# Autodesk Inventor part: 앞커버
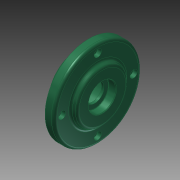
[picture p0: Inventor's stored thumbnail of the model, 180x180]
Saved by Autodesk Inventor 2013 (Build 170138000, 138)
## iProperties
Created: 2015-11
Part Number: 앞커버
Material: 알루미늄 6061
Document SubType Name: Modeling
Designer: mduedu
Density: 2.71 g/cm^3
Mass: 261.017 g
Surface Area: 221.215 cm^2
Volume: 96.3164 cm^3
Author: mduedu
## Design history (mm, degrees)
sketch "스케치1"
  geometry: C1 r 47.5 at (0, 0); 1 further point
  constraints: 1 centre point, 1 coincident
  dimensions: "d57" = 95 diameter of C1
extrude "돌출1" new body sketch "스케치1" distance "d3" = 10; taper "d4" = 0 deg
sketch "스케치2"
  geometry: C1 r 30 at (0, 0); 1 further point
  constraints: 1 centre point, 1 coincident
  dimensions: "d5" = 60 diameter of C1
extrude "돌출2" join sketch "스케치2" distance "d6" = 5; taper "d7" = -30 deg
sketch "스케치3" dims "d58" = 78
  geometry: 3 further points
  constraints: 2 vertical alignment, 1 coincident, 2 other
hole "구멍1" sketch "스케치3" at (0, 39) diameter "d11" = 4.5; stored, may be unused: countersink angle "d15" = 90 deg, drill point angle "d17" = 118 deg; dims "d12" = 6, "d13" = 8, "d14" = 4.4, "d16" = 8
sketch "스케치4"
  geometry: C1 r 32.5 at (0, 0); 1 further point
  constraints: 1 centre point, 1 coincident
  dimensions: "d21" = 65 diameter of C1
extrude "돌출3" join sketch "스케치4" distance "d23" = 12; taper "d24" = 0 deg
hole "구멍2" diameter "d27" = 34; stored, may be unused: countersink angle "d31" = 90 deg, drill point angle "d33" = 0 deg; dims "d28" = 6, "d29" = 40, "d30" = 12, "d32" = 16, "d68" = 10, "d69" = 10
fillet "모깎기3" dims "d36" = 3
fillet "모깎기4" dims "d37" = 3
fillet "모깎기5" dims "d38" = 0.3
chamfer "모따기1" distance "d39" = 1; stored, may be unused: second distance "d40" = 2, angle "d41" = 45 deg
hole "구멍3" diameter "d44" = 20; stored, may be unused: countersink angle "d48" = 90 deg, drill point angle "d50" = 118 deg; dims "d45" = 6, "d46" = 30, "d47" = 8.3, "d49" = 8, "d59" = 10, "d60" = 10
fillet "모깎기6" dims "d51" = 0.3
chamfer "모따기2" distance "d52" = 0.8; stored, may be unused: second distance "d53" = 2, angle "d54" = 30 deg
node "솔리드1"
pattern_circular "원형 패턴1" dims angle "d19" = 360 deg
